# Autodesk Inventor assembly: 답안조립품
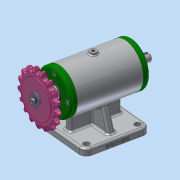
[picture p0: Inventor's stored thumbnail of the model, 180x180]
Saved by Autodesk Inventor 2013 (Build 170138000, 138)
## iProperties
Created: 2019-06
Part Number: 답안조립품
Document SubType Name: Assembly
Designer: Administrator
Author: Administrator
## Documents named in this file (11)
- C:\Users\Administrator\Desktop\490604V1031\답안조립품.iam
- C:\Users\Administrator\Desktop\490604V1031\본체.ipt
- C:\Users\Administrator\Desktop\490604V1031\베어링 6203.ipt
- C:\Users\Administrator\Desktop\490604V1031\볼트 M4.ipt
- C:\Users\Administrator\Desktop\490604V1031\스프로킷.ipt
- C:\Users\Administrator\Desktop\490604V1031\스프링와셔.ipt
- C:\Users\Administrator\Desktop\490604V1031\오일 실 17 30 5.ipt
- C:\Users\Administrator\Desktop\490604V1031\축.ipt
- C:\Users\Administrator\Desktop\490604V1031\커버.ipt
- C:\Users\Administrator\Desktop\490604V1031\키 4x4x12.ipt
- C:\Users\Administrator\Desktop\490604V1031\평와셔.ipt
